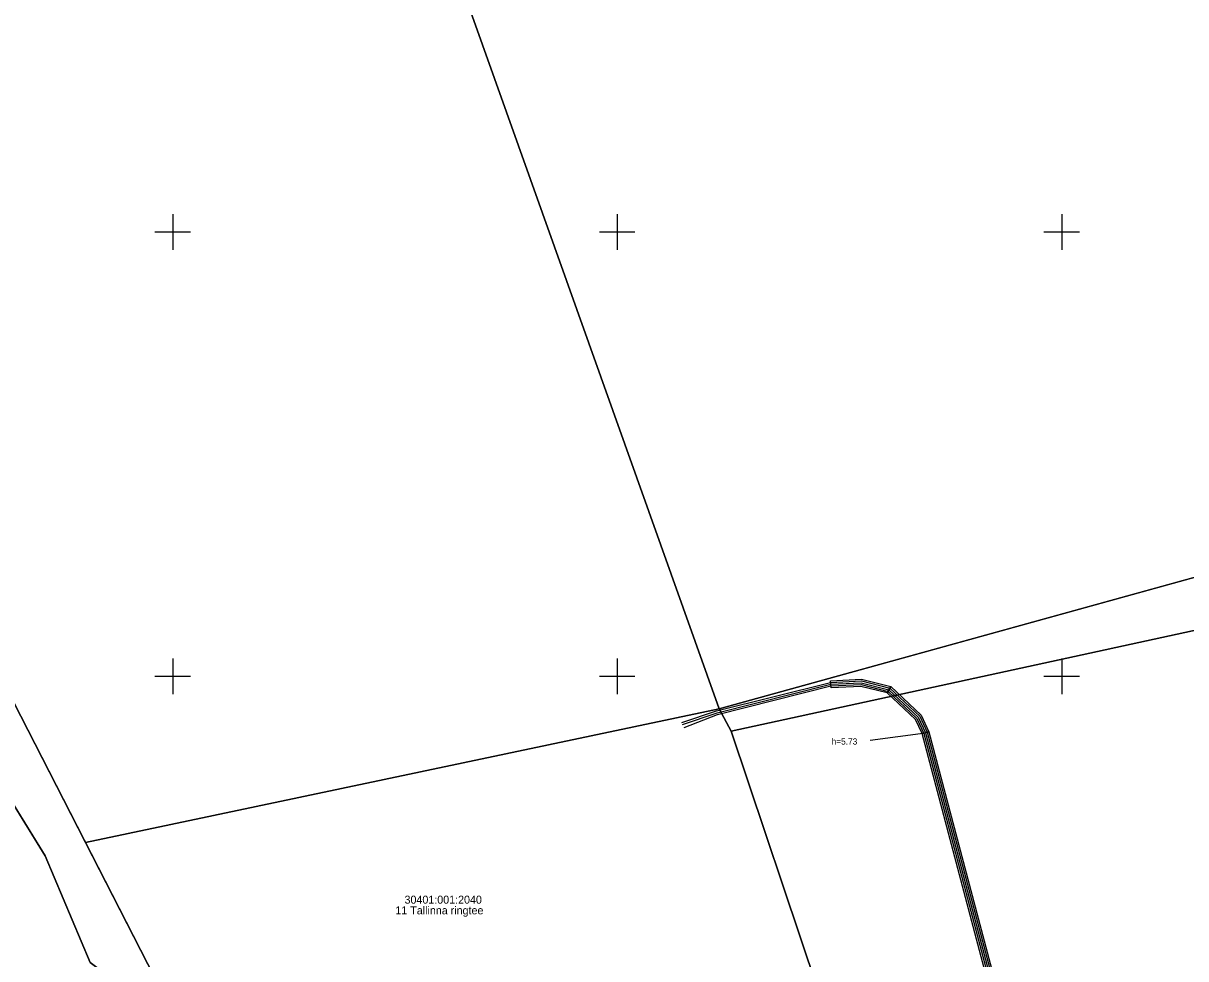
# Model space of a CAD drawing. Extents: x 543497 to 552146, y 6567125 to 6579845.
# Drawn here: x 546533.2 to 546664, y 6577818.2 to 6577923.5 of the extents above; entities that cross this region are included whole.
import ezdxf

# ---------------------------------------------------------------- set-up
doc = ezdxf.new("R2010")
doc.units = 0
for name, color, linetype in [('xref_Kangru tee 1_geodeesia$0$ABIJOONIS', 7, 'Continuous'), ('xref_Kangru tee 1_geodeesia$0$ELRAJATISMA', 7, 'Continuous'), ('xref_Kangru tee 1_geodeesia$0$KPKAABEL', 7, 'Continuous'), ('xref_Kangru tee 1_geodeesia$0$PIIR', 7, 'Continuous'), ('xref_Kangru tee 1_geodeesia$0$vork', 7, 'Continuous')]:
    doc.layers.add(name, color=color, linetype=linetype)

# ---------------------------------------------------------------- blocks, each defined once
blk = doc.blocks.new('xref_Kangru tee 1_geodeesia$0$VKORIS')
for p, q in [((0, 4), (0, -4)), ((-4, 0), (4, 0))]:
    blk.add_line(p, q)

msp = doc.modelspace()

# ---------------------------------------------------------------- linework, layer by layer
at = {"layer": 'xref_Kangru tee 1_geodeesia$0$ABIJOONIS'}
msp.add_lwpolyline([(546628.46, 6577842.81), (546634.69, 6577843.63)], dxfattribs=at)
at = {"layer": 'xref_Kangru tee 1_geodeesia$0$ELRAJATISMA'}
for points in [[(546624.08, 6577848.72), (546624.01, 6577849.51), (546627.5, 6577849.68), (546630.77, 6577848.85), (546630.38, 6577848.13), (546627.42, 6577848.87), (546624.08, 6577848.72)], [(546630.77, 6577848.85), (546634.2, 6577845.63), (546635.07, 6577843.76), (546634.3, 6577843.56), (546633.54, 6577845.15), (546630.38, 6577848.13), (546630.77, 6577848.85)], [(546654.01, 6577769.04), (546634.3, 6577843.56), (546635.07, 6577843.76), (546654.79, 6577769.25), (546654.01, 6577769.04)]]:
    msp.add_lwpolyline(points, dxfattribs=at)
at = {"layer": 'xref_Kangru tee 1_geodeesia$0$KPKAABEL'}
for points in [[(546607.27, 6577844.82), (546611.19, 6577846.11), (546623.99, 6577849.31), (546627.48, 6577849.48), (546630.67, 6577848.67), (546634.03, 6577845.51), (546634.88, 6577843.7), (546654.66, 6577768.95), (546653.64, 6577766.6), (546652.18, 6577765.51), (546651.52, 6577763.63), (546650.2, 6577761.5), (546649.81, 6577760.88), (546650.49, 6577759.15)], [(546607.35, 6577844.57), (546611.23, 6577845.91), (546624.02, 6577849.11), (546627.46, 6577849.27), (546630.57, 6577848.49), (546633.87, 6577845.39), (546634.69, 6577843.63), (546654.44, 6577768.98), (546653.47, 6577766.73), (546652.01, 6577765.64), (546651.33, 6577763.7), (546650.02, 6577761.59), (546649.59, 6577760.89), (546650.31, 6577759.07)], [(546607.55, 6577844.25), (546611.27, 6577845.72), (546624.05, 6577848.92), (546627.44, 6577849.07), (546630.47, 6577848.31), (546633.7, 6577845.27), (546634.5, 6577843.56), (546654.23, 6577769.01), (546653.31, 6577766.85), (546651.84, 6577765.76), (546651.14, 6577763.77), (546649.84, 6577761.68), (546649.36, 6577760.91), (546650.12, 6577759)]]:
    msp.add_lwpolyline(points, dxfattribs=at)
at = {"layer": 'xref_Kangru tee 1_geodeesia$0$PIIR'}
for points in [[(546948.2, 6577919.45), (546801.95, 6577884.96), (546612.83, 6577843.82), (546611.48, 6577846.34), (546681.56, 6577865.74), (546741.83, 6577888.61), (546804.12, 6577918.64), (546823.72, 6577935.62), (546840.87, 6577968.94), (546842.58, 6578000.95), (546830.7, 6578057.64), (546794.77, 6578166.4), (546728.27, 6578308.16), (546677.39, 6578395.18), (546581.04, 6578525.99)], [(546479.96, 6578264.05), (546660.75, 6578417.77), (546677.39, 6578395.18), (546728.27, 6578308.16), (546794.77, 6578166.4), (546830.7, 6578057.64), (546842.58, 6578000.95), (546840.87, 6577968.94), (546792.14, 6577916.99), (546673.57, 6577863.53), (546611.48, 6577846.34), (546521.16, 6578099.75), (546496.8, 6578164.74), (546476.38, 6578219.21), (546479.96, 6578264.05)], [(546398.05, 6577968.6), (546410.54, 6577981.91), (546456.64, 6578031.02), (546521.16, 6578099.75), (546611.48, 6577846.34), (546540.2, 6577831.29), (546532.12, 6577847.04), (546448.34, 6577926.98), (546398.05, 6577968.6)], [(546393.84, 6577964.11), (546398.05, 6577968.6), (546448.34, 6577926.98), (546532.12, 6577847.04), (546551.12, 6577809.99), (546540.71, 6577817.81), (546535.64, 6577829.79), (546527.76, 6577842.6), (546517.98, 6577854.65), (546508.9, 6577863.97), (546488.79, 6577882.98), (546469.41, 6577900.33), (546393.84, 6577964.11)], [(547009.94, 6577883.45), (546729.34, 6577816.03), (546702.66, 6577807.95), (546633.51, 6577792.62), (546622.52, 6577814.88), (546612.83, 6577843.82), (546801.95, 6577884.96), (546948.2, 6577919.45)], [(546540.2, 6577831.29), (546611.48, 6577846.34), (546612.83, 6577843.82), (546622.52, 6577814.88), (546561.59, 6577802.16), (546551.12, 6577809.99), (546540.2, 6577831.29)], [(546508.03, 6577841.48), (546527.76, 6577842.6), (546535.64, 6577829.79), (546540.71, 6577817.81), (546551.12, 6577809.99), (546561.59, 6577802.16), (546622.52, 6577814.88), (546633.51, 6577792.62), (546608.95, 6577787.91), (546573.78, 6577780.87), (546521.59, 6577770.69), (546316.12, 6577725.86), (546173.38, 6577691.06), (546034.23, 6577654.21), (545899.95, 6577611.29), (545780.54, 6577566.57), (545623.97, 6577499.02), (545555.77, 6577467.67), (545385.83, 6577376.92), (545249.19, 6577295.85), (545250.22, 6577289.9), (544980.83, 6577118.49)]]:
    msp.add_lwpolyline(points, dxfattribs=at)

# ---------------------------------------------------------------- block references
at = {"layer": 'xref_Kangru tee 1_geodeesia$0$vork', "xscale": 0.5, "yscale": 0.5}
for p in [(546550, 6577900), (546600, 6577900), (546650, 6577900), (546550, 6577850), (546600, 6577850), (546650, 6577850)]:
    msp.add_blockref('xref_Kangru tee 1_geodeesia$0$VKORIS', p, dxfattribs=at)

# ---------------------------------------------------------------- texts
at = {"layer": 'xref_Kangru tee 1_geodeesia$0$ABIJOONIS'}
msp.add_text('h=5.73', height=0.7, dxfattribs=at).set_placement((546624.12, 6577842.32))
at = {"layer": 'xref_Kangru tee 1_geodeesia$0$PIIR'}
for s, p in [('30401:001:2040', (546576.08, 6577824.42)), ('11 Tallinna ringtee', (546575.05, 6577823.22))]:
    msp.add_text(s, height=0.9, dxfattribs=at).set_placement(p)

doc.saveas('drawing.dxf')
